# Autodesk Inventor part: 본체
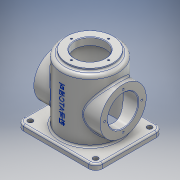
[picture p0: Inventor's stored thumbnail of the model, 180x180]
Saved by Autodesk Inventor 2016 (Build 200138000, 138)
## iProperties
Created: 2021-02
Part Number: 본체
Material: 알루미늄 6061
Document SubType Name: Modeling
Designer: user
Density: 2.7 g/cm^3
Appearance: 알루미늄 - 평지
Mass: 1186.99 g
Surface Area: 1041.94 cm^2
Volume: 439.628 cm^3
Author: user
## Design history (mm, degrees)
sketch "스케치12"
  geometry: L1 (70, -60)-(-70, -60); L2 (-70, -60)-(-70, 60); L3 (-70, 60)-(70, 60); L4 (70, 60)-(70, -60); L5 (70, -60)-(-70, 60); L6 (-70, -60)-(70, 60); 1 further point
  constraints: 12 end point, 2 midpoint, 2 parallel, 1 horizontal, 1 perpendicular
  dimensions: "d99" = 140 distance of L2.end L3.end; "d100" = 120 distance of L1.end L2.end
extrude "돌출5" new body sketch "스케치12" distance "d101" = 10; taper "d102" = 0 deg
fillet "모깎기5" dims "d103" = 12
hole "구멍7" diameter "d106" = 9; stored, may be unused: countersink angle "d110" = 90 deg, drill point angle "d112" = 118 deg; dims "d104" = 10, "d105" = 10, "d107" = 8, "d108" = 4, "d109" = 2, "d111" = 10
sketch "스케치13"
  geometry: C1 r 50 at (0, 0); 1 further point
  constraints: 1 centre point, 1 coincident
  dimensions: "d119" = 100 diameter of C1
extrude "돌출6" join sketch "스케치13" distance "d120" = 110; taper "d121" = 0 deg
sketch "스케치15"
  geometry: C1 r 42 at (0, 0); 1 further point
  constraints: 1 centre point, 1 coincident
  dimensions: "d122" = 84 diameter of C1
sketch "스케치16"
  geometry: C1 r 41 at (0, 0); 1 further point
  constraints: 1 centre point, 1 coincident
  dimensions: "d123" = 82 diameter of C1
extrude "돌출7" join sketch "스케치16" distance "d124" = 5; taper "d125" = 0 deg
hole "구멍8" sketch "스케치15" diameter "d126" = 54; stored, may be unused: countersink angle "d130" = 90 deg, drill point angle "d132" = 118 deg; dims "d127" = 8, "d128" = 84, "d129" = 112, "d131" = 10
fillet "모깎기6" dims "d133" = 3
fillet "모깎기7" dims "d134" = 3
node "작업 평면7"
sketch "스케치17"
  geometry: L1 (48, 0)-(-48, 0) reference; C1 r 41 at (0, 60); 2 further points
  constraints: 1 centre point, 1 midpoint, 1 vertical alignment
  dimensions: "d136" = 82 diameter of C1; "d137" = 60 distance from line of L1 C1.centre
extrude "돌출8" join sketch "스케치17" stored distance "d138" = 5; taper "d139" = 0 deg
hole "구멍9" diameter "d142" = 54; stored, may be unused: countersink angle "d146" = 90 deg, drill point angle "d148" = 118 deg; dims "d140" = 10, "d141" = 10, "d143" = 8, "d144" = 84, "d145" = 112, "d147" = 10
sketch "스케치18"
  geometry: L1 (0, 0)-(-33, 0); C1 r 27 at (0, 0) reference; 1 further point
  constraints: 2 end point, 1 coincident, 1 horizontal
  dimensions: "d149" = 33 distance of L1.start L1.end
hole "구멍10" sketch "스케치18" at (-33, 0) diameter "d150" = 3.242; stored, may be unused: countersink angle "d154" = 90 deg, drill point angle "d156" = 118 deg; dims "d151" = 8, "d152" = 84, "d153" = 112, "d155" = 10
sketch "스케치19"
  geometry: L1 (0, 0)-(-33, 0)
  constraints: 2 end point, 1 horizontal
  dimensions: "d160" = 33 distance of L1.start L1.end
hole "구멍11" sketch "스케치19" at (-33, 0) diameter "d161" = 3.242; stored, may be unused: countersink angle "d165" = 90 deg, drill point angle "d167" = 118 deg; dims "d162" = 8, "d163" = 84, "d164" = 112, "d166" = 10
chamfer "모따기2" distance "d171" = 1; stored, may be unused: second distance "d172" = 2, angle "d173" = 45 deg
fillet "모깎기8" dims "d174" = 6
fillet "모깎기9" dims "d175" = 3
node "작업 평면8"
sketch "스케치20"
  geometry: L1 (-58, 0)-(58, 0) reference; 3 further points
  constraints: 1 midpoint, 1 vertical alignment, 1 other
  dimensions: "d177" = 66 distance from line of L1 point (0, 66)
feature "엠보싱3" sketch "스케치20" dims "d99" = 140, "d100" = 120, "d118" = 116, "d178" = 0.5, "d179" = 0
node "솔리드2"
pattern_linear "직사각형 패턴2" dims "d115" = 96, "d118" = 116
mirror "대칭3"
pattern_circular "원형 패턴3" dims angle "d158" = 360 deg
mirror "대칭4"
pattern_circular "원형 패턴4" dims angle "d169" = 360 deg
other parameters: "d135" = 59, "d176" = -54.75
